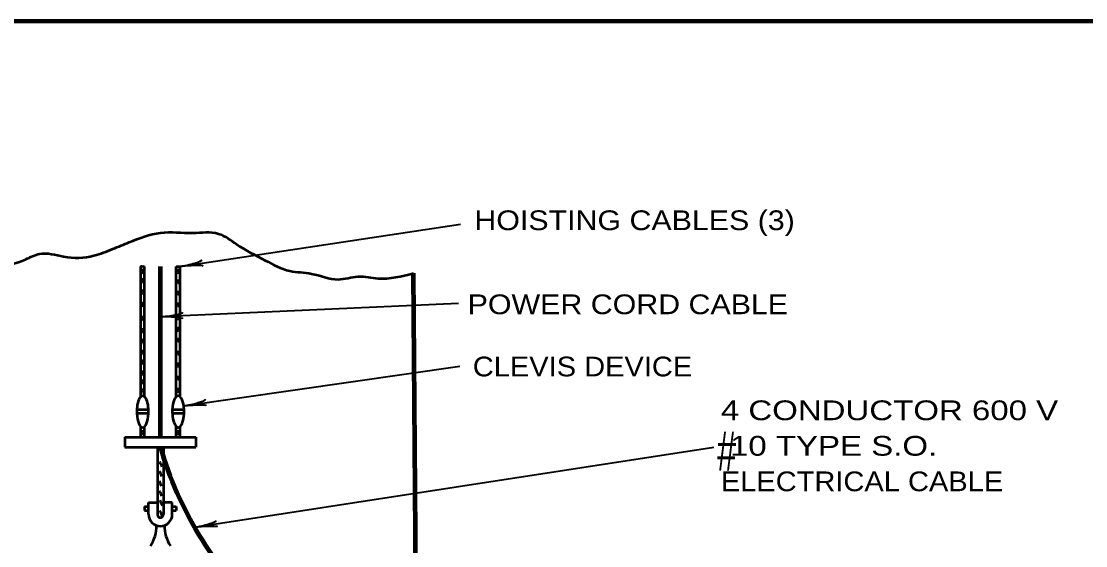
# Model space of a CAD drawing. Extents: x -24 to 689, y -7 to 446.
# Drawn here: x 399.8 to 534.7, y 374.2 to 440.6 of the extents above; entities that cross this region are included whole.
import ezdxf
from ezdxf.enums import TextEntityAlignment as Align

# ---------------------------------------------------------------- set-up
doc = ezdxf.new("R2010")
doc.units = 0
doc.layers.add('1', color=7, linetype='Continuous', lineweight=35)

msp = doc.modelspace()

# ---------------------------------------------------------------- linework, layer by layer
at = {"layer": '1'}
for p, q in [((419.95, 409.606), (455.443, 414.94)), ((417.45, 403.246), (455.206, 404.943)), ((420.4, 391.942), (455.396, 396.984)), ((421.756, 376.569), (487.534, 386.706))]:
    msp.add_line(p, q, dxfattribs=at)
at = {"layer": '1', "lineweight": 53}
for p, q in [((414.95, 393.106), (414.95, 409.606)), ((415.45, 393.106), (415.45, 409.606)), ((419.45, 393.106), (419.45, 409.606)), ((419.95, 393.106), (419.95, 409.606)), ((414.456, 391.47), (415.944, 391.47)), ((418.956, 391.47), (420.444, 391.47)), ((415.944, 390.97), (414.456, 390.97)), ((420.444, 390.97), (418.956, 390.97)), ((414.95, 387.971), (414.95, 389.335)), ((415.45, 387.971), (415.45, 389.335)), ((419.45, 387.971), (419.45, 389.335)), ((419.95, 387.971), (419.95, 389.335)), ((412.95, 387.971), (421.95, 387.971)), ((412.95, 387.971), (412.95, 386.721)), ((421.95, 387.971), (421.95, 386.721)), ((412.95, 386.721), (421.95, 386.721)), ((417.075, 386.721), (417.075, 378.218)), ((417.825, 386.721), (417.825, 378.221)), ((415.45, 379.218), (415.95, 379.218)), ((415.45, 379.218), (415.45, 378.718)), ((415.95, 378.218), (415.95, 379.718)), ((415.95, 379.718), (417.075, 379.718)), ((418.95, 379.721), (417.825, 379.721)), ((418.95, 378.221), (418.95, 379.721)), ((418.95, 379.218), (419.45, 379.218)), ((419.45, 379.218), (419.45, 378.718)), ((415.45, 378.718), (415.95, 378.718)), ((418.95, 378.718), (419.45, 378.718))]:
    msp.add_line(p, q, dxfattribs=at)
at = {"layer": '1', "lineweight": 200}
msp.add_line((417.45, 387.971), (417.45, 409.606), dxfattribs=at)
at = {"layer": '1', "lineweight": 106}
msp.add_line((450.738, 257.745), (449.488, 408.744), dxfattribs=at)
at = {"layer": '1', "lineweight": 158}
msp.add_lwpolyline([(683.413, 440.647), (23.663, 440.564), (23.747, 2.23)], dxfattribs=at)
at = {"layer": '1', "lineweight": 200}
msp.add_arc((461.415, 399.379), 45.751, 196.06279, 226.51634, dxfattribs=at)
at = {"layer": '1', "lineweight": 53}
for centre, radius, start, end in [((417.45, 378.221), 1.5, 180.08989, 0), ((417.45, 378.197), 0.376, 176.82066, 3.53584), ((412.445, 376.744), 4.506, 326.28532, 0.79097), ((422.457, 376.744), 4.506, 179.20914, 213.71468)]:
    msp.add_arc(centre, radius, start, end, dxfattribs=at)
at = {"layer": '1', "lineweight": 40}
for centre, major_axis, ratio, start_param, end_param in [((420.988, 410.041), (-1.743, -0.42), 0.122415, 0.8963533, 3.1415927), ((420.988, 410.041), (-1.743, -0.42), 0.122415, 0.8963533, 3.1415927), ((421.09, 409.563), (1.763, 0.087), 0.07063, 6.2823074, 8.5597026), ((421.09, 409.563), (1.763, 0.087), 0.07063, 6.2823074, 8.5597026), ((418.528, 403.572), (-1.777, -0.236), 0.122415, 0.8963533, 3.1415927), ((418.528, 403.572), (-1.777, -0.236), 0.122415, 0.8963533, 3.1415927), ((418.579, 403.085), (1.763, -0.097), 0.07063, 6.2823074, 8.5597026), ((418.579, 403.085), (1.763, -0.097), 0.07063, 6.2823074, 8.5597026), ((421.44, 392.371), (-1.745, -0.409), 0.122415, 0.8963533, 3.1415927), ((421.44, 392.371), (-1.745, -0.409), 0.122415, 0.8963533, 3.1415927), ((421.539, 391.892), (1.764, 0.077), 0.07063, 6.2823074, 8.5597026), ((421.539, 391.892), (1.764, 0.077), 0.07063, 6.2823074, 8.5597026), ((422.792, 377.008), (-1.741, -0.426), 0.122415, 0.8963533, 3.1415927), ((422.792, 377.008), (-1.741, -0.426), 0.122415, 0.8963533, 3.1415927), ((422.896, 376.531), (-1.763, -0.094), 0.07063, 3.1407148, 5.41811), ((422.896, 376.531), (-1.763, -0.094), 0.07063, 3.1407148, 5.41811)]:
    msp.add_ellipse(centre, major_axis=major_axis, ratio=ratio, start_param=start_param, end_param=end_param, dxfattribs=at)
at = {"layer": '1', "lineweight": 53}
for centre, start_param, end_param in [((415.2, 391.22), 1.4454628, 4.8377225), ((419.7, 391.22), 1.6961242, 4.5870612), ((415.2, 391.22), 4.5870612, 4.8377168), ((415.2, 391.22), 1.4454685, 1.6961242), ((419.7, 391.22), 4.5870554, 7.9793152), ((419.7, 391.22), 4.5870612, 4.8377168), ((419.7, 391.22), 1.4454685, 1.6961242), ((415.2, 391.22), 4.8377168, 7.7286538)]:
    msp.add_ellipse(centre, major_axis=(0, -2), ratio=0.375, start_param=start_param, end_param=end_param, dxfattribs=at)
for points in [[(395.488, 408.744), (396.751, 409.29), (400.362, 410.494), (402.168, 411.216), (405.177, 410.855), (409.029, 410.975), (411.437, 411.818), (413.483, 412.661), (417.456, 413.865), (421.548, 413.865), (424.799, 413.745), (427.086, 412.42), (430.697, 410.373), (433.827, 409.049), (436.596, 408.688), (439.966, 407.965), (442.494, 408.326), (445.022, 408.085), (449.488, 408.744)], [(414.95, 409.606), (415.085, 409.631), (415.251, 409.609), (415.372, 409.616), (415.45, 409.606)], [(415.123, 409.298), (415.15, 409.079), (415.26, 408.696)], [(419.45, 409.606), (419.594, 409.578), (419.745, 409.586), (419.836, 409.601), (419.95, 409.606)], [(419.636, 409.298), (419.664, 409.079), (419.773, 408.696)], [(415.178, 408.121), (415.205, 407.902), (415.315, 407.519)], [(419.664, 407.957), (419.691, 407.738), (419.8, 407.355)], [(415.178, 406.698), (415.205, 406.48), (415.315, 406.096)], [(419.664, 406.507), (419.691, 406.288), (419.8, 405.905)], [(415.123, 405.111), (415.15, 404.893), (415.26, 404.51)], [(419.664, 405.029), (419.691, 404.81), (419.8, 404.427)], [(415.178, 403.36), (415.205, 403.141), (415.315, 402.758)], [(419.636, 403.415), (419.664, 403.196), (419.773, 402.813)], [(419.582, 401.965), (419.609, 401.746), (419.719, 401.363)], [(415.178, 401.801), (415.205, 401.582), (415.315, 401.199)], [(419.664, 400.569), (419.691, 400.35), (419.8, 399.967)], [(415.205, 400.432), (415.232, 400.214), (415.342, 399.83)], [(415.15, 397.806), (415.178, 397.587), (415.287, 397.204)], [(415.205, 399.037), (415.232, 398.818), (415.342, 398.435)], [(419.664, 398.928), (419.691, 398.709), (419.8, 398.326)], [(415.178, 396.438), (415.205, 396.219), (415.315, 395.836)], [(419.636, 397.423), (419.664, 397.204), (419.773, 396.821)], [(415.15, 395.343), (415.178, 395.124), (415.287, 394.741)], [(419.664, 395.753), (419.691, 395.535), (419.8, 395.152)], [(415.205, 394.166), (415.232, 393.948), (415.342, 393.565)], [(419.636, 394.221), (419.664, 394.002), (419.773, 393.619)], [(415.178, 388.886), (415.205, 388.667), (415.315, 388.284)], [(419.636, 388.858), (419.664, 388.639), (419.773, 388.256)], [(417.34, 384.892), (417.525, 384.459), (417.618, 384.211)], [(417.309, 383.686), (417.494, 383.253), (417.587, 383.006)], [(417.278, 382.449), (417.464, 382.017), (417.556, 381.769)], [(417.309, 381.182), (417.494, 380.749), (417.587, 380.502)], [(417.371, 380.007), (417.556, 379.575), (417.649, 379.327)], [(417.34, 378.709), (417.525, 378.276), (417.618, 378.029)]]:
    msp.add_spline(points, degree=3, dxfattribs=at)

# ---------------------------------------------------------------- texts
at = {"layer": '1'}
for s, height, width, p in [('HOISTING CABLES (3)', 2.5, 1.15, (477.514, 414.202)), ('POWER CORD CABLE', 2.5, 1.15, (476.663, 403.559)), ('CLEVIS DEVICE', 2.5, 1.1, (470.917, 395.683)), ('#', 5, 0.65, (489.172, 383.727))]:
    msp.add_text(s, height=height, dxfattribs=dict(at, width=width)).set_placement(p, align=Align.CENTER)
for s, width, p in [('4 CONDUCTOR 600 V', 1.25, (488.441, 390.139)), (' 10 TYPE S.O.', 1.25, (488.441, 385.639)), ('ELECTRICAL CABLE', 1.1, (488.441, 381.139))]:
    msp.add_text(s, height=2.5, dxfattribs=dict(at, width=width)).set_placement(p)

doc.saveas('drawing.dxf')
